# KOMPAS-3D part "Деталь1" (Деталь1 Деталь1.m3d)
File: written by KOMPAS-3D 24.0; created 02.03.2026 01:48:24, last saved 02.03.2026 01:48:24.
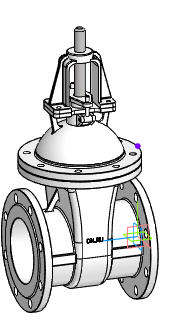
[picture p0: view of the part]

Document properties: Автор: R2D2; Полное имя файла: E:\Работа\Зайцев\GVWR3131M-2W-F-S Задвижка клиновая с выдвижным штоком DN.ru Ду50-200 Ру63\DN150\исходные материалы\Деталь1 Деталь1.m3d

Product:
- Body: Твердое тело1  | qty 1  | 5 such rows
- Part/product: Деталь1
    additional columns: Типовые

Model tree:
1. Твердое тело1  (labels: Твердое тело1)
2. Точка:1
     Y = 216.5; Координата Y = 216.5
